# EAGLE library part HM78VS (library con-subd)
SUB-D
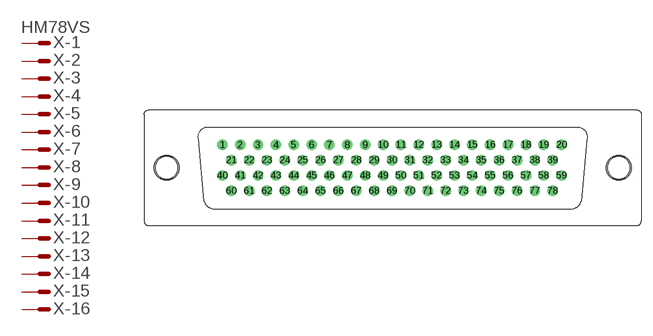
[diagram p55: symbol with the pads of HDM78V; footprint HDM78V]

Designator prefix X; gates -1=MV -2=M -3=M -4=M -5=M -6=M -7=M -8=M -9=M -10=M -11=M -12=M -13=M -14=M -15=M -16=M -17=M -18=M -19=M -20=M -21=M -22=M -23=M -24=M -25=M -26=M -27=M -28=M -29=M -30=M -31=M -32=M -33=M -34=M -35=M -36=M -37=M -38=M -39=M -40=M -41=M -42=M -43=M -44=M -45=M -46=M -47=M -48=M -49=M -50=M -51=M -52=M -53=M -54=M -55=M -56=M -57=M -58=M -59=M -60=M -61=M -62=M -63=M -64=M -65=M -66=M -67=M -68=M -69=M -70=M -71=M -72=M -73=M -74=M -75=M -76=M -77=M -78=M

## HM78VS (OC_FARNELL: unknown; OC_NEWARK: unknown)  [HDM78V]
1  -1:M  pas
2  -2:M  pas
3  -3:M  pas
4  -4:M  pas
5  -5:M  pas
6  -6:M  pas
7  -7:M  pas
8  -8:M  pas
9  -9:M  pas
10  -10:M  pas
11  -11:M  pas
12  -12:M  pas
13  -13:M  pas
14  -14:M  pas
15  -15:M  pas
16  -16:M  pas
17  -17:M  pas
18  -18:M  pas
19  -19:M  pas
20  -20:M  pas
21  -21:M  pas
22  -22:M  pas
23  -23:M  pas
24  -24:M  pas
25  -25:M  pas
26  -26:M  pas
27  -27:M  pas
28  -28:M  pas
29  -29:M  pas
30  -30:M  pas
31  -31:M  pas
32  -32:M  pas
33  -33:M  pas
34  -34:M  pas
35  -35:M  pas
36  -36:M  pas
37  -37:M  pas
38  -38:M  pas
39  -39:M  pas
40  -40:M  pas
41  -41:M  pas
42  -42:M  pas
43  -43:M  pas
44  -44:M  pas
45  -45:M  pas
46  -46:M  pas
47  -47:M  pas
48  -48:M  pas
49  -49:M  pas
50  -50:M  pas
51  -51:M  pas
52  -52:M  pas
53  -53:M  pas
54  -54:M  pas
55  -55:M  pas
56  -56:M  pas
57  -57:M  pas
58  -58:M  pas
59  -59:M  pas
60  -60:M  pas
61  -61:M  pas
62  -62:M  pas
63  -63:M  pas
64  -64:M  pas
65  -65:M  pas
66  -66:M  pas
67  -67:M  pas
68  -68:M  pas
69  -69:M  pas
70  -70:M  pas
71  -71:M  pas
72  -72:M  pas
73  -73:M  pas
74  -74:M  pas
75  -75:M  pas
76  -76:M  pas
77  -77:M  pas
78  -78:M  pas

## Footprint HDM78V (pad centres in mm)
SUB-D
drill 0.9 round: 1 -23.024,3.12; 2 -20.611,3.12; 3 -18.198,3.12; 4 -15.785,3.12; 5 -13.372,3.12; 6 -10.959,3.12; 7 -8.546,3.12; 8 -6.133,3.12; 9 -3.72,3.12; 10 -1.307,3.12; 11 1.106,3.12; 12 3.519,3.12; 13 5.932,3.12; 14 8.345,3.12; 15 10.758,3.12; 16 13.171,3.12; 17 15.584,3.12; 18 17.997,3.12; 19 20.41,3.12; 20 22.823,3.12; 21 -21.817,1.04; 22 -19.404,1.04; 23 -16.991,1.04; 24 -14.578,1.04; 25 -12.165,1.04; 26 -9.752,1.04; 27 -7.339,1.04; 28 -4.926,1.04; 29 -2.513,1.04; 30 -0.1,1.04; 31 2.313,1.04; 32 4.726,1.04; 33 7.139,1.04; 34 9.552,1.04; 35 11.965,1.04; 36 14.378,1.04; 37 16.791,1.04; 38 19.204,1.04; 39 21.617,1.04; 40 -23.024,-1.04; 41 -20.611,-1.04; 42 -18.198,-1.04; 43 -15.785,-1.04; 44 -13.372,-1.04; 45 -10.959,-1.04; 46 -8.546,-1.04; 47 -6.133,-1.04; 48 -3.72,-1.04; 49 -1.307,-1.04; 50 1.106,-1.04; 51 3.519,-1.04; 52 5.932,-1.04; 53 8.345,-1.04; 54 10.758,-1.04; 55 13.171,-1.04; 56 15.584,-1.04; 57 17.997,-1.04; 58 20.41,-1.04; 59 22.823,-1.04; 60 -21.817,-3.12; 61 -19.404,-3.12; 62 -16.991,-3.12; 63 -14.578,-3.12; 64 -12.165,-3.12; 65 -9.752,-3.12; 66 -7.339,-3.12; 67 -4.926,-3.12; 68 -2.513,-3.12; 69 -0.1,-3.12; 70 2.313,-3.12; 71 4.726,-3.12; 72 7.139,-3.12; 73 9.552,-3.12; 74 11.965,-3.12; 75 14.378,-3.12; 76 16.791,-3.12; 77 19.204,-3.12; 78 21.617,-3.12
hole 3 at -30.55,0
hole 3 at 30.55,0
